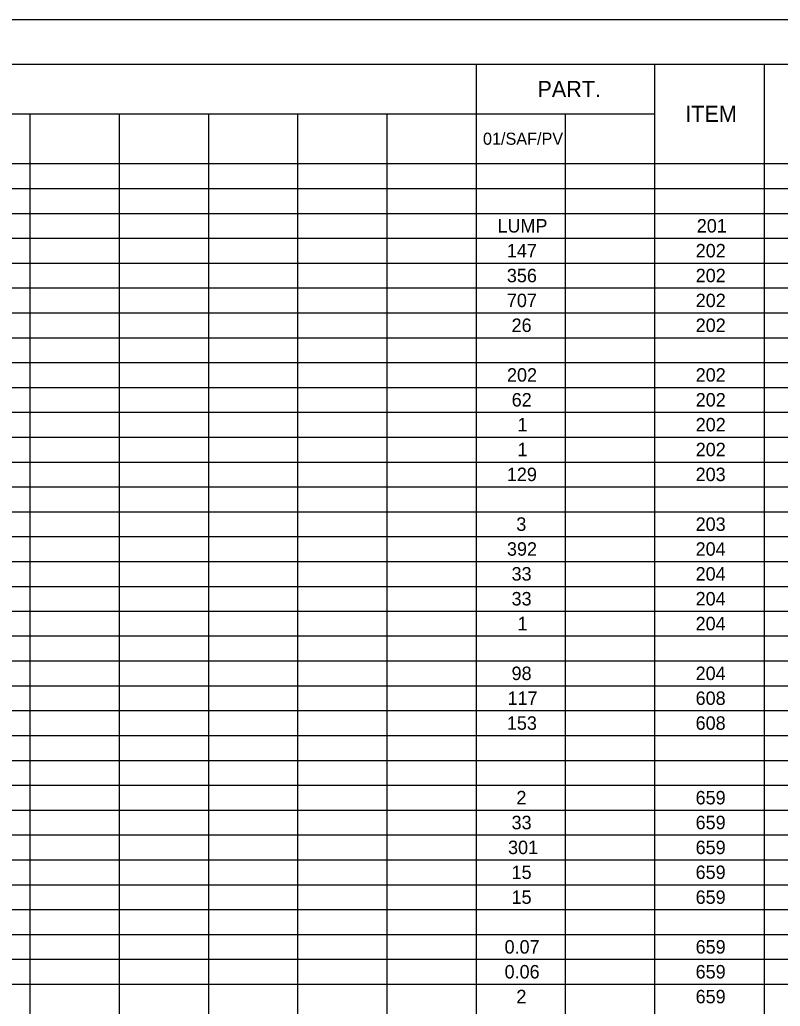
# Model space of a CAD drawing. Extents: x 0 to 34, y 0 to 22.
# Drawn here: x 8.42 to 16.98, y 10.89 to 22 of the extents above; entities that cross this region are included whole.
import ezdxf

# ---------------------------------------------------------------- set-up
doc = ezdxf.new("R2010")
doc.units = 0
for name, color, linetype in [('SH_Border', 7, 'Continuous'), ('SH_Cut_Line', 7, 'Continuous'), ('SH_Text', 7, 'Continuous')]:
    doc.layers.add(name, color=color, linetype=linetype)

msp = doc.modelspace()

# ---------------------------------------------------------------- linework, layer by layer
at = {"layer": 'SH_Border'}
msp.add_lwpolyline([(1.5, 21.5), (33.5, 21.5), (33.5, 0.5), (1.5, 0.5)], close=True, dxfattribs=at)
at = {"layer": 'SH_Cut_Line'}
msp.add_lwpolyline([(0, 0), (34, 0), (34, 22), (0, 22)], close=True, dxfattribs=at)
at = {"layer": 'SH_Text'}
for p, q in [((1.5, 21.5), (32.001, 21.5)), ((13.556, 21.5), (13.556, 0.502)), ((15.565, 21.5), (15.565, 0.502)), ((16.8, 21.5), (16.8, 0.502)), ((1.5, 20.94), (15.565, 20.94)), ((8.532, 20.94), (8.532, 0.502)), ((9.537, 20.94), (9.537, 0.502)), ((10.542, 20.94), (10.542, 0.502)), ((11.546, 20.94), (11.546, 0.502)), ((12.551, 20.94), (12.551, 0.502)), ((14.56, 20.94), (14.56, 0.502)), ((1.5, 20.38), (32.001, 20.38)), ((1.5, 20.1), (32.001, 20.1)), ((1.5, 19.82), (32.001, 19.82)), ((1.5, 19.54), (32.001, 19.54)), ((1.5, 19.26), (32.001, 19.26)), ((1.5, 18.98), (32.001, 18.98)), ((1.5, 18.7), (32.001, 18.7)), ((1.5, 18.42), (32.001, 18.42)), ((1.5, 18.14), (32.001, 18.14)), ((1.5, 17.86), (32.001, 17.86)), ((1.5, 17.58), (32.001, 17.58)), ((1.5, 17.3), (32.001, 17.3)), ((1.5, 17.02), (32.001, 17.02)), ((1.5, 16.74), (32.001, 16.74)), ((1.5, 16.46), (32.001, 16.46)), ((1.5, 16.18), (32.001, 16.18)), ((1.5, 15.9), (32.001, 15.9)), ((1.5, 15.62), (32.001, 15.62)), ((1.5, 15.34), (32.001, 15.34)), ((1.5, 15.061), (32.001, 15.061)), ((1.5, 14.781), (32.001, 14.781)), ((1.5, 14.501), (32.001, 14.501)), ((1.5, 14.221), (32.001, 14.221)), ((1.5, 13.941), (32.001, 13.941)), ((1.5, 13.661), (32.001, 13.661)), ((1.5, 13.381), (32.001, 13.381)), ((1.5, 13.101), (32.001, 13.101)), ((1.5, 12.821), (32.001, 12.821)), ((1.5, 12.541), (32.001, 12.541)), ((1.5, 12.261), (32.001, 12.261)), ((1.5, 11.981), (32.001, 11.981)), ((1.5, 11.701), (32.001, 11.701)), ((1.5, 11.421), (32.001, 11.421)), ((1.5, 11.141), (32.001, 11.141))]:
    msp.add_line(p, q, dxfattribs=at)

# ---------------------------------------------------------------- texts
for s, height, p in [('PART.', 0.1818, (14.247, 21.129)), ('ITEM', 0.1818, (15.911, 20.849)), ('01/SAF/PV', 0.1364, (13.634, 20.592)), ('LUMP', 0.1515, (13.797, 19.604)), ('201', 0.1515, (16.041, 19.604)), ('147', 0.1515, (13.903, 19.324)), ('202', 0.1515, (16.029, 19.324)), ('356', 0.1515, (13.903, 19.044)), ('202', 0.1515, (16.029, 19.044)), ('707', 0.1515, (13.903, 18.764)), ('202', 0.1515, (16.029, 18.764)), ('26', 0.1515, (13.956, 18.484)), ('202', 0.1515, (16.029, 18.484)), ('202', 0.1515, (13.904, 17.925)), ('202', 0.1515, (16.029, 17.925)), ('62', 0.1515, (13.957, 17.645)), ('202', 0.1515, (16.029, 17.645)), ('1', 0.152, (14.022, 17.365)), ('202', 0.1515, (16.029, 17.365)), ('1', 0.152, (14.022, 17.085)), ('202', 0.1515, (16.029, 17.085)), ('129', 0.1515, (13.903, 16.805)), ('203', 0.1515, (16.028, 16.805)), ('3', 0.152, (14.009, 16.245)), ('203', 0.1515, (16.028, 16.245)), ('392', 0.1515, (13.904, 15.965)), ('204', 0.1515, (16.028, 15.965)), ('33', 0.1515, (13.956, 15.685)), ('204', 0.1515, (16.028, 15.685)), ('33', 0.1515, (13.956, 15.405)), ('204', 0.1515, (16.028, 15.405)), ('1', 0.152, (14.022, 15.125)), ('204', 0.1515, (16.028, 15.125)), ('98', 0.1515, (13.956, 14.565)), ('204', 0.1515, (16.028, 14.565)), ('117', 0.1515, (13.91, 14.285)), ('608', 0.1515, (16.028, 14.285)), ('153', 0.1515, (13.903, 14.005)), ('608', 0.1515, (16.028, 14.005)), ('2', 0.152, (14.01, 13.165)), ('659', 0.1515, (16.028, 13.165)), ('33', 0.1515, (13.956, 12.885)), ('659', 0.1515, (16.028, 12.885)), ('301', 0.1515, (13.916, 12.605)), ('659', 0.1515, (16.028, 12.605)), ('15', 0.1515, (13.956, 12.325)), ('659', 0.1515, (16.028, 12.325)), ('15', 0.1515, (13.956, 12.045)), ('659', 0.1515, (16.028, 12.045)), ('0.07', 0.1515, (13.877, 11.485)), ('659', 0.1515, (16.028, 11.485)), ('0.06', 0.1515, (13.877, 11.205)), ('659', 0.1515, (16.028, 11.205)), ('2', 0.152, (14.01, 10.925)), ('659', 0.1515, (16.028, 10.925))]:
    msp.add_text(s, height=height, dxfattribs=at).set_placement(p)

doc.saveas('drawing.dxf')
